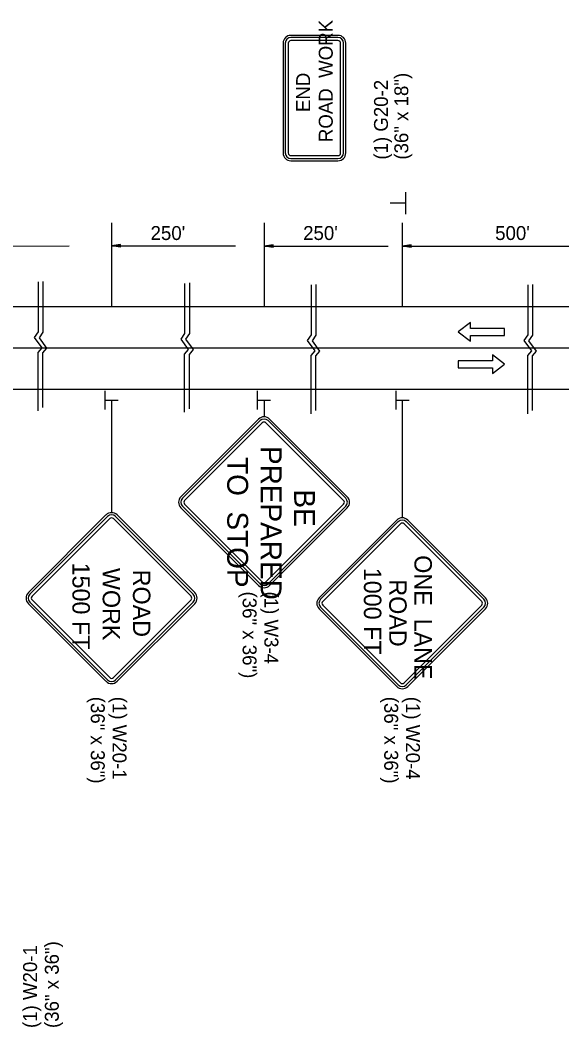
# Model space of a CAD drawing. Extents: x 1927831 to 1930787, y 596452 to 597699.
# Drawn here: x 1928240.2 to 1928473.3, y 597195.5 to 597628.8 of the extents above; entities that cross this region are included whole.
import ezdxf

# ---------------------------------------------------------------- set-up
doc = ezdxf.new("R2010")
doc.units = 0
for name, color, linetype in [('Default', 7, 'Continuous'), ('P_TC_Signs_Permanent', 7, 'Continuous'), ('P_TC_Signs_Temporary', 7, 'Continuous'), ('R_Border', 7, 'Continuous'), ('R_Striping', 7, 'Continuous')]:
    doc.layers.add(name, color=color, linetype=linetype)

msp = doc.modelspace()

# ---------------------------------------------------------------- linework, layer by layer
at = {"layer": 'Default'}
for p, q in [((1928406.01, 597554.74), (1928406.01, 597545.26)), ((1928405.87, 597550.02), (1928399.4, 597550.02)), ((1928279.55, 597541.61), (1928279.55, 597505.58)), ((1928345.2, 597541.61), (1928345.2, 597505.58)), ((1928404.65, 597541.61), (1928404.65, 597505.58)), ((1928207.95, 597531.57), (1928261.36, 597531.59)), ((1928283.39, 597532.16), (1928279.55, 597531.59)), ((1928279.55, 597531.59), (1928332.95, 597531.59)), ((1928283.39, 597531.01), (1928279.55, 597531.59)), ((1928283.39, 597532.07), (1928280.19, 597531.59)), ((1928283.39, 597531.11), (1928280.19, 597531.59)), ((1928283.39, 597531.97), (1928280.85, 597531.59)), ((1928283.39, 597531.2), (1928280.85, 597531.59)), ((1928283.39, 597531.87), (1928281.49, 597531.59)), ((1928283.39, 597531.3), (1928281.49, 597531.59)), ((1928283.39, 597531.77), (1928282.14, 597531.59)), ((1928283.39, 597531.4), (1928282.14, 597531.59)), ((1928283.39, 597531.68), (1928282.78, 597531.59)), ((1928283.39, 597531.5), (1928282.78, 597531.59)), ((1928283.39, 597531.01), (1928283.39, 597532.16)), ((1928349.04, 597532.14), (1928345.2, 597531.57)), ((1928345.2, 597531.57), (1928398.6, 597531.57)), ((1928349.04, 597530.99), (1928345.2, 597531.57)), ((1928349.04, 597532.05), (1928345.84, 597531.57)), ((1928349.04, 597531.09), (1928345.84, 597531.57)), ((1928349.04, 597531.95), (1928346.5, 597531.57)), ((1928349.04, 597531.18), (1928346.5, 597531.57)), ((1928349.04, 597531.85), (1928347.14, 597531.57)), ((1928349.04, 597531.28), (1928347.14, 597531.57)), ((1928349.04, 597531.75), (1928347.79, 597531.57)), ((1928349.04, 597531.38), (1928347.79, 597531.57)), ((1928349.04, 597531.66), (1928348.43, 597531.57)), ((1928349.04, 597531.48), (1928348.43, 597531.57)), ((1928349.04, 597530.99), (1928349.04, 597532.14)), ((1928408.49, 597532.14), (1928404.65, 597531.57)), ((1928404.65, 597531.57), (1928504.41, 597531.57)), ((1928408.49, 597530.99), (1928404.65, 597531.57)), ((1928408.49, 597532.05), (1928405.3, 597531.57)), ((1928408.49, 597531.09), (1928405.3, 597531.57)), ((1928408.49, 597531.95), (1928405.96, 597531.57)), ((1928408.49, 597531.18), (1928405.96, 597531.57)), ((1928408.49, 597531.85), (1928406.59, 597531.57)), ((1928408.49, 597531.28), (1928406.59, 597531.57)), ((1928408.49, 597531.75), (1928407.24, 597531.57)), ((1928408.49, 597531.38), (1928407.24, 597531.57)), ((1928408.49, 597531.66), (1928407.89, 597531.57)), ((1928408.49, 597531.48), (1928407.89, 597531.57)), ((1928408.49, 597530.99), (1928408.49, 597532.14)), ((1928044.85, 597505.58), (1929173.7, 597505.58)), ((1927908.3, 597487.79), (1929173.7, 597487.79)), ((1928044.85, 597470), (1929173.7, 597470)), ((1928276.87, 597461.2), (1928276.87, 597469.2)), ((1928342.35, 597461.2), (1928342.35, 597469.2)), ((1928401.98, 597461.2), (1928401.98, 597469.2)), ((1928276.99, 597465.18), (1928282.45, 597465.18)), ((1928342.47, 597465.18), (1928347.93, 597465.18)), ((1928402.1, 597465.18), (1928407.56, 597465.18))]:
    msp.add_line(p, q, dxfattribs=at)
for points in [[(1928247.96, 597516.18), (1928247.96, 597494.66), (1928246.3, 597492.19), (1928249.53, 597487.76), (1928247.83, 597485.71), (1928247.82, 597460.68)], [(1928250, 597516.37), (1928250, 597494.57), (1928248.34, 597492.1), (1928251.58, 597487.67), (1928249.87, 597485.62), (1928249.87, 597462.12)], [(1928311, 597515.51), (1928311, 597493.99), (1928309.34, 597491.51), (1928312.58, 597487.08), (1928310.87, 597485.04), (1928310.87, 597460.01)], [(1928313.04, 597515.7), (1928313.04, 597493.9), (1928311.38, 597491.43), (1928314.62, 597487), (1928312.91, 597484.95), (1928312.91, 597461.45)], [(1928365.46, 597514.86), (1928365.46, 597493.34), (1928363.8, 597490.87), (1928367.04, 597486.44), (1928365.33, 597484.39), (1928365.33, 597459.37)], [(1928367.5, 597515.06), (1928367.5, 597493.25), (1928365.84, 597490.78), (1928369.08, 597486.35), (1928367.38, 597484.31), (1928367.37, 597460.81)], [(1928458.63, 597514.86), (1928458.63, 597493.34), (1928456.96, 597490.87), (1928460.2, 597486.44), (1928458.5, 597484.39), (1928458.49, 597459.37)], [(1928460.67, 597515.06), (1928460.67, 597493.25), (1928459.01, 597490.78), (1928462.25, 597486.35), (1928460.54, 597484.31), (1928460.54, 597460.81)]]:
    msp.add_lwpolyline(points, dxfattribs=at)
at = {"layer": 'P_TC_Signs_Permanent'}
for p, q in [((1928342.81, 597457.08), (1928309.4, 597423.67)), ((1928343.48, 597456.42), (1928310.07, 597423.01)), ((1928344.41, 597455.49), (1928310.99, 597422.08)), ((1928379.41, 597422.08), (1928346, 597455.49)), ((1928380.34, 597423.01), (1928346.92, 597456.42)), ((1928381, 597423.67), (1928347.59, 597457.08)), ((1928309.4, 597418.89), (1928342.81, 597385.48)), ((1928310.07, 597419.56), (1928343.48, 597386.15)), ((1928310.99, 597420.49), (1928344.41, 597387.08)), ((1928346, 597387.08), (1928379.41, 597420.49)), ((1928346.92, 597386.15), (1928380.34, 597419.56)), ((1928347.59, 597385.48), (1928381, 597418.89))]:
    msp.add_line(p, q, dxfattribs=at)
for centre, radius, start, end in [((1928345.2, 597454.69), 3.37, 45, 135), ((1928345.2, 597454.69), 2.44, 45, 135), ((1928345.2, 597454.69), 1.13, 45, 135), ((1928311.79, 597421.28), 3.37, 135, 225), ((1928378.61, 597421.28), 3.37, 315, 45), ((1928311.79, 597421.28), 2.44, 135, 225), ((1928311.79, 597421.28), 1.13, 135, 225), ((1928378.61, 597421.28), 1.13, 315, 45), ((1928378.61, 597421.28), 2.44, 315, 45), ((1928345.2, 597387.87), 3.37, 225, 315), ((1928345.2, 597387.87), 2.44, 225, 315), ((1928345.2, 597387.87), 1.13, 225, 315)]:
    msp.add_arc(centre, radius, start, end, dxfattribs=at)
at = {"layer": 'P_TC_Signs_Temporary'}
for p, q in [((1928353.35, 597618.86), (1928353.35, 597571.61)), ((1928354.29, 597618.86), (1928354.29, 597571.61)), ((1928355.6, 597618.86), (1928355.6, 597571.61)), ((1928376.98, 597622.24), (1928356.73, 597622.24)), ((1928376.98, 597621.3), (1928356.73, 597621.3)), ((1928376.98, 597619.99), (1928356.73, 597619.99)), ((1928378.1, 597571.61), (1928378.1, 597618.86)), ((1928379.41, 597571.61), (1928379.41, 597618.86)), ((1928380.35, 597571.61), (1928380.35, 597618.86)), ((1928356.73, 597570.49), (1928376.98, 597570.49)), ((1928356.73, 597569.17), (1928376.98, 597569.17)), ((1928356.73, 597568.24), (1928376.98, 597568.24)), ((1928243.75, 597382.42), (1928277.16, 597415.83)), ((1928244.41, 597381.76), (1928277.82, 597415.17)), ((1928281.27, 597415.17), (1928314.68, 597381.76)), ((1928281.93, 597415.83), (1928315.35, 597382.42)), ((1928245.34, 597380.83), (1928278.75, 597414.24)), ((1928280.34, 597414.24), (1928313.75, 597380.83)), ((1928368.86, 597380.2), (1928402.27, 597413.61)), ((1928369.52, 597379.54), (1928402.93, 597412.95)), ((1928370.45, 597378.61), (1928403.86, 597412.02)), ((1928405.45, 597412.02), (1928438.86, 597378.61)), ((1928406.38, 597412.95), (1928439.79, 597379.54)), ((1928407.04, 597413.61), (1928440.45, 597380.2)), ((1928277.16, 597344.24), (1928243.75, 597377.65)), ((1928277.82, 597344.9), (1928244.41, 597378.31)), ((1928278.75, 597345.83), (1928245.34, 597379.24)), ((1928313.75, 597379.24), (1928280.34, 597345.83)), ((1928314.68, 597378.31), (1928281.27, 597344.9)), ((1928315.35, 597377.65), (1928281.93, 597344.24)), ((1928402.27, 597342.02), (1928368.86, 597375.43)), ((1928402.93, 597342.68), (1928369.52, 597376.09)), ((1928403.86, 597343.61), (1928370.45, 597377.02)), ((1928438.86, 597377.02), (1928405.45, 597343.61)), ((1928439.79, 597376.09), (1928406.38, 597342.68)), ((1928440.45, 597375.43), (1928407.04, 597342.02))]:
    msp.add_line(p, q, dxfattribs=at)
for centre, radius, start, end in [((1928356.73, 597618.86), 3.37, 90, 180), ((1928356.73, 597618.86), 2.44, 90, 180), ((1928356.73, 597618.86), 1.13, 90, 180), ((1928376.98, 597618.86), 3.37, 360, 90), ((1928376.98, 597618.86), 2.44, 360, 90), ((1928376.98, 597618.86), 1.13, 360, 90), ((1928356.73, 597571.61), 3.37, 180, 270), ((1928356.73, 597571.61), 2.44, 180, 270), ((1928356.73, 597571.61), 1.13, 180, 270), ((1928376.98, 597571.61), 2.44, 270, 360), ((1928376.98, 597571.61), 1.13, 270, 360), ((1928376.98, 597571.61), 3.37, 270, 360), ((1928279.55, 597413.45), 3.37, 45, 135), ((1928279.55, 597413.45), 2.44, 45, 135), ((1928279.55, 597413.45), 1.12, 45, 135), ((1928404.65, 597411.22), 3.37, 45, 135), ((1928404.65, 597411.22), 2.44, 45, 135), ((1928404.65, 597411.22), 1.12, 45, 135), ((1928246.14, 597380.04), 3.37, 135, 225), ((1928246.14, 597380.04), 2.44, 135, 225), ((1928246.14, 597380.04), 1.13, 135, 225), ((1928312.96, 597380.04), 1.13, 315, 45), ((1928312.96, 597380.04), 2.44, 315, 45), ((1928312.96, 597380.04), 3.37, 315, 45), ((1928371.24, 597377.81), 3.37, 135, 225), ((1928438.06, 597377.81), 3.37, 315, 45), ((1928371.24, 597377.81), 2.44, 135, 225), ((1928371.24, 597377.81), 1.13, 135, 225), ((1928438.06, 597377.81), 1.13, 315, 45), ((1928438.06, 597377.81), 2.44, 315, 45), ((1928279.55, 597346.63), 1.12, 225, 315), ((1928279.55, 597346.63), 3.37, 225, 315), ((1928279.55, 597346.63), 2.44, 225, 315), ((1928404.65, 597344.4), 3.37, 225, 315), ((1928404.65, 597344.4), 2.44, 225, 315), ((1928404.65, 597344.4), 1.12, 225, 315)]:
    msp.add_arc(centre, radius, start, end, dxfattribs=at)
at = {"layer": 'R_Border'}
for p, q in [((1928279.55, 597465.18), (1928279.55, 597416.82)), ((1928345.2, 597465.18), (1928345.2, 597458.07)), ((1928404.65, 597465.18), (1928404.65, 597414.6))]:
    msp.add_line(p, q, dxfattribs=at)
at = {"layer": 'R_Striping'}
for points in [[(1928433.95, 597498.63), (1928428.75, 597494.63), (1928433.95, 597490.63), (1928433.95, 597493.13), (1928448.66, 597493.13), (1928448.66, 597496.13), (1928433.95, 597496.13)], [(1928443.47, 597476.68), (1928448.66, 597480.68), (1928443.47, 597484.68), (1928443.47, 597482.18), (1928428.75, 597482.18), (1928428.75, 597479.18), (1928443.47, 597479.18)]]:
    msp.add_lwpolyline(points, close=True, dxfattribs=at)

# ---------------------------------------------------------------- texts
at = {"layer": 'Default'}
for s, p in [("250'", (1928296.35, 597534.16)), ("250'", (1928362, 597534.16)), ("500'", (1928444.63, 597534.16))]:
    msp.add_text(s, height=6, rotation=360, dxfattribs=at).set_placement(p)
at = {"layer": 'P_TC_Signs_Temporary'}
for s, height, rotation, p in [('ROAD  WORK', 6, 90, (1928374.73, 597576.28)), ('END', 6, 90, (1928364.98, 597589.21)), ('TO  STOP', 9, 270, (1928329.33, 597440.75)), ('PREPARED', 9, 270, (1928343.73, 597445.52)), ('BE', 9, 270, (1928358.13, 597426.83)), ('ONE  LANE', 7.5, 270, (1928409.9, 597398.51)), ('1500 FT', 7.5, 270, (1928262.71, 597395.33)), ('WORK', 7.5, 270, (1928275.74, 597393.03)), (' ROAD ', 7.5, 270, (1928288.76, 597395.06)), ('1000 FT', 7.5, 270, (1928388.15, 597393.1)), ('ROAD', 7.5, 270, (1928399.03, 597388.12))]:
    msp.add_text(s, height=height, rotation=rotation, dxfattribs=at).set_placement(p)
at = {"layer": 'R_Border'}
for s, height, rotation, p in [('(36" x 18")', 5.9996, 90, (1928407.25, 597568.75)), ('(1) G20-2', 6, 90, (1928398.5, 597568.75)), ('(36" x 36")', 5.9996, 270, (1928335.97, 597382.88)), ('(1) W3-4', 6, 270, (1928345.33, 597382.88)), ('(36" x 36")', 5.9996, 270, (1928270.63, 597337.6)), ('(1) W20-1', 6, 270, (1928279.99, 597337.6)), ('(36" x 36")', 5.9996, 270, (1928396.89, 597337.6)), ('(1) W20-4', 6, 270, (1928406.25, 597337.6)), ('(1) W20-1', 6, 90, (1928247.49, 597195.04)), ('(36" x 36")', 5.9996, 90, (1928256.85, 597195.04))]:
    msp.add_text(s, height=height, rotation=rotation, dxfattribs=at).set_placement(p)

doc.saveas('drawing.dxf')
